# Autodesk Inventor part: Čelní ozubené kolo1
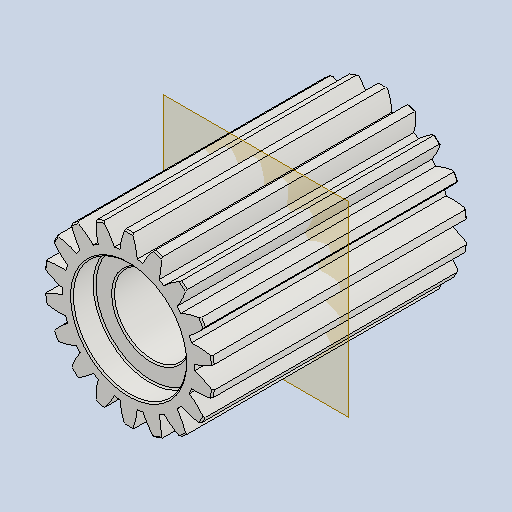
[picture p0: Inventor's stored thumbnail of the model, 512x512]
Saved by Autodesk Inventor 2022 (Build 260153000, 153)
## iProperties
CustomPartVersion: 1
Created: 2025-05
Part Number: Čelní ozubené kolo1
Material: Steel
Document SubType Name: Modeling
Designer: jbart
Categories: <?xml version="1.0" encoding="UTF-16"?> <MemberInstance><Categories><FamilyTemplate><FamilyTemplateParameter ValueType="xs:double" Id="1" ObjectReferenceKey="da
Density: 7.85 g/cm^3
Appearance: Steel
Mass: 8914.05 g
Surface Area: 1687.53 cm^2
Volume: 1135.55 cm^3
Author: jbart
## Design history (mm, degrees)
sketch "Sketch1"
  geometry: C1 r 59.993 at (0, 0)
  constraints: 1 centre point
  dimensions: "d0" = 119.98507 diameter of C1 (= da_da)
extrude "Extrusion1" new body sketch "Sketch1" distance "d1" = 180 (= da_b); taper "d2" = 0 deg
workplane "Work Plane2"
sketch "Sketch2"
  geometry: C1 r 59.993 at (0, 0) reference; C2 r 54 at (0, 0)
  constraints: 1 centre point, 1 coincident
  dimensions: "d3" = 108 diameter of C2 (= da_d)
feature "Roztečný průměr" sketch "Sketch2" dims "d4" = 10, "d5" = 0
workplane "Work Plane8"
workplane "Work Plane9"
feature "Čelní ozubené kolo" dims "d34" = 10 deg (computed from da_z), "da_b" = 180, "da_d" = 108, "da_aw" = 189.61491, "da_da" = 119.98507, "da_df" = 93, "da_dw" = 108.35138, angle "da_beta" = 0 deg, "da_lefttooth" = 0, "da_righttooth" = 0
sketch "Náčrt3"
  geometry: C1 r 40 at (0, 0); 1 further point
  constraints: 1 centre point, 1 coincident
  dimensions: "d49" = 80 diameter of C1
extrude "Vysunutí2" cut sketch "Náčrt3" distance "d50" = 16; taper "d51" = 0 deg
node "Pracovní rovina11"
mirror "Zrcadlit1"
sketch "Náčrt4"
  geometry: C1 r 27 at (0, 0); 1 further point
  constraints: 1 centre point, 1 coincident
  dimensions: "d53" = 54 diameter of C1
extrude "Vysunutí3" cut sketch "Náčrt4" extent not by distance; stored distance "d54" = 0; taper "d55" = 0 deg
chamfer "Zkosení1" distance "d56" = 1; stored, may be unused: second distance "d57" = 2, angle "d58" = 45 deg
fillet "Zaoblení1" dims "d59" = 1
chamfer "Zkosení2" distance "d60" = 1; stored, may be unused: second distance "d61" = 2, angle "d62" = 45 deg
body "Solid1"
body "Srf1"
other parameters: "d16" = 189.61491 (= da_aw), "d17" = 0, "d39" = 0, "d41" = 0, "d43" = 189.61491 (= da_aw), "d46" = 189.61491 (= da_aw), "d47" = 0, "d48" = 0
